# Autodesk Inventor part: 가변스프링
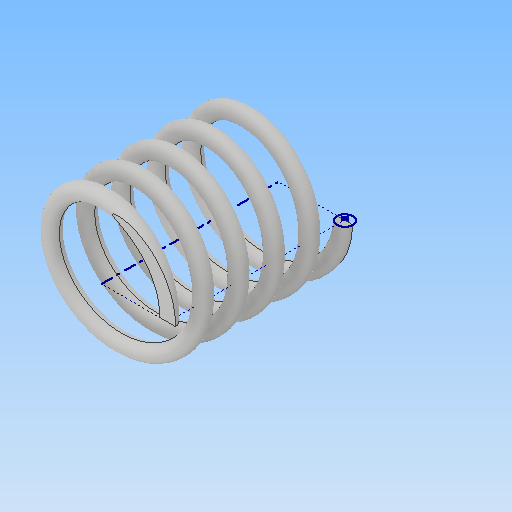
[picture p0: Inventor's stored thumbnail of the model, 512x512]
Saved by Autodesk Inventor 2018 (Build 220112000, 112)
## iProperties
Created: 2022-09
Part Number: 가변스프링
Material: 일반
Document SubType Name: Modeling
Designer: home
Density: 1 g/cm^3
Appearance: 기본값
Mass: 0.82315 g
Surface Area: 16.7317 cm^2
Volume: 0.82315 cm^3
Author: home
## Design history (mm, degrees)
sketch "스케치2"
  geometry: L1 (0, 0)-(-8.5, 0); L2 (-8.5, 0)-(-8.5, 22.5); L3 (-8.5, 22.5)-(0, 22.5); L4 (0, 22.5)-(0, 0); C1 r 1 at (-8.5, 0)
  constraints: 8 end point, 2 parallel, 1 centre point, 1 coincident, 1 horizontal, 1 perpendicular
  dimensions: "d0" = 17 diameter of L2 L4; "d1" = 22.5 distance of L1.end L2.end (derived); "d2" = 2 diameter of C1
feature "코일1" sketch "스케치2" pitch "d3" = 10; turns "d5" = 5; dims "d4" = 22.5 (= d1), "d6" = 0, angle "d7" = 90 deg, angle "d8" = 90 deg, "d9" = 0, "d10" = 0
node "작업 평면1"
sketch "스케치3"
  geometry: L1 (1, 0)-(-1, 0) reference; 1 further point
  constraints: 1 horizontal alignment
extrude "돌출1" cut sketch "스케치3" extent not by distance; stored distance "d11" = 10; taper "d12" = 0 deg
sketch "스케치4"
  geometry: L1 (7.5, 0)-(9.5, 0) reference; 1 further point
  constraints: 1 horizontal alignment
extrude "돌출2" cut sketch "스케치4" extent not by distance; stored distance "d13" = 10; taper "d14" = 0 deg
node "솔리드1"
node "절단 모서리 투영1"
node "절단 모서리 투영2"
